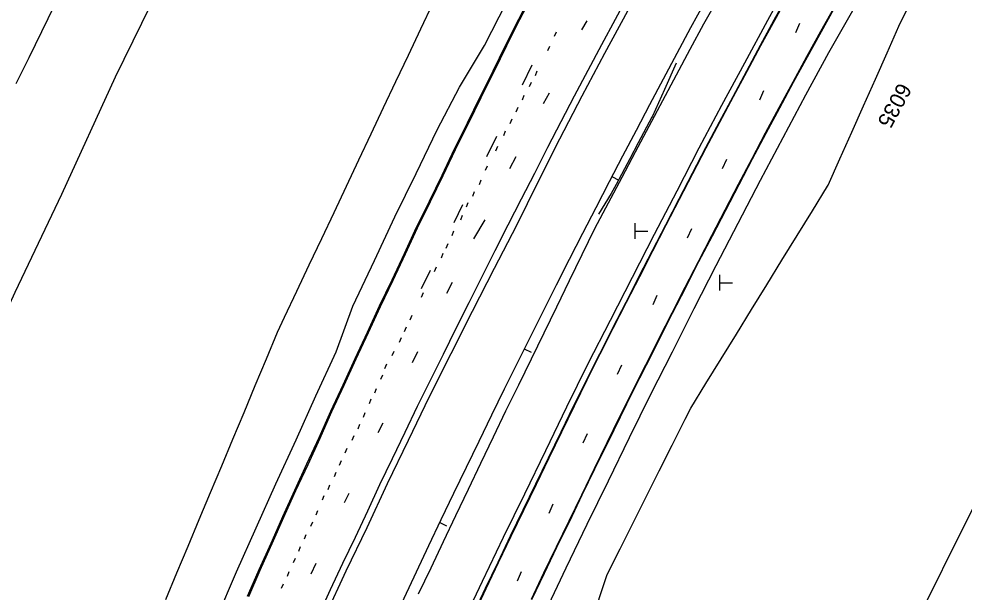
# Model space of a CAD drawing. Extents: x 2132221 to 2141942, y 535736 to 547298.
# Drawn here: x 2136377.6 to 2136866.6, y 538086.4 to 538383 of the extents above; entities that cross this region are included whole.
import ezdxf

# ---------------------------------------------------------------- set-up
doc = ezdxf.new("R2010")
doc.units = 0
for name, color, linetype in [('RD_EX_BldgApp', 7, 'Continuous'), ('RD_EX_Conc', 7, 'Continuous'), ('RD_EX_Fence_Other', 7, 'Continuous'), ('RD_EX_GuardRail', 7, 'Continuous'), ('RD_EX_Misc', 7, 'Continuous'), ('RD_EX_Road', 7, 'Continuous'), ('RD_EX_VEG', 7, 'Continuous'), ('RD_HC_Cl', 7, 'Continuous'), ('RD_HC_Data_Tic', 7, 'Continuous'), ('RD_HC_TX_Sta50', 7, 'Continuous'), ('TOPO_E_TLIML-Line', 7, 'Continuous')]:
    doc.layers.add(name, color=color, linetype=linetype)

msp = doc.modelspace()

# ---------------------------------------------------------------- linework, layer by layer
at = {"layer": 'RD_EX_BldgApp'}
for p, q in [((2136696.19, 538277.36), (2136696.19, 538273.25)), ((2136696.19, 538273.25), (2136696.19, 538269.13)), ((2136696.19, 538273.25), (2136703.05, 538273.25)), ((2136740.01, 538250.62), (2136740.01, 538246.51)), ((2136740.01, 538246.51), (2136740.01, 538242.39)), ((2136740.01, 538246.51), (2136746.87, 538246.51))]:
    msp.add_line(p, q, dxfattribs=at)
at = {"layer": 'RD_EX_Conc'}
for points in [[(2136495.93, 538084.29), (2136501.94, 538098.03), (2136508.09, 538111.72), (2136514.19, 538125.42), (2136520.29, 538139.13), (2136526.63, 538152.72), (2136532.88, 538166.36), (2136538.99, 538180.05), (2136545.27, 538193.68), (2136551.59, 538207.29), (2136557.87, 538220.91), (2136564.22, 538234.5), (2136570.66, 538248.05), (2136577.03, 538261.63), (2136583.37, 538275.23), (2136589.96, 538288.71), (2136596.5, 538302.2), (2136602.97, 538315.74), (2136609.6, 538329.2), (2136616.3, 538342.62), (2136622.9, 538356.08), (2136629.56, 538369.53), (2136636.31, 538382.93), (2136643.07, 538396.32)], [(2136612.65, 538074.77), (2136619.07, 538088.33), (2136625.52, 538101.87), (2136631.99, 538115.41), (2136638.55, 538128.9), (2136645.1, 538142.39), (2136651.64, 538155.89), (2136658.2, 538169.38), (2136664.77, 538182.87), (2136671.39, 538196.33), (2136678.1, 538209.75), (2136684.9, 538223.12), (2136691.74, 538236.47), (2136698.58, 538249.82), (2136705.4, 538263.18), (2136712.26, 538276.52), (2136719.19, 538289.82), (2136726.1, 538303.13), (2136733.02, 538316.45), (2136740.04, 538329.7), (2136747.09, 538342.94), (2136754.16, 538356.17), (2136761.28, 538369.37), (2136768.43, 538382.56), (2136775.68, 538395.69)], [(2136643.01, 538082.62), (2136649.46, 538096.16), (2136655.98, 538109.67), (2136662.55, 538123.15), (2136669.09, 538136.65), (2136675.64, 538150.14), (2136682.22, 538163.62), (2136688.83, 538177.08), (2136695.48, 538190.53), (2136702.25, 538203.91), (2136709.03, 538217.29), (2136715.81, 538230.67), (2136722.61, 538244.04), (2136729.42, 538257.4), (2136736.36, 538270.7), (2136743.31, 538283.99), (2136750.22, 538297.31), (2136757.19, 538310.59), (2136764.22, 538323.84), (2136771.3, 538337.06), (2136778.4, 538350.27), (2136785.56, 538363.45), (2136792.81, 538376.58), (2136800.14, 538389.66)]]:
    msp.add_lwpolyline(points, dxfattribs=at)
at = {"layer": 'RD_EX_Fence_Other'}
for points in [[(2136450.24, 538399.41), (2136427.31, 538352.83), (2136399.57, 538292.12), (2136375.56, 538241.34), (2136349.06, 538184.13), (2136326.14, 538129.95), (2136298.73, 538065.31), (2136267.48, 537990.84), (2136241.5, 537929.73), (2136222.24, 537881.77), (2136189.74, 537799.13)], [(2136917.56, 538219.98), (2136890.82, 538168.74), (2136867.21, 538121.82), (2136843.5, 538074.27), (2136814.83, 538016.13), (2136789.9, 537964.36), (2136765.69, 537912.51), (2136738.54, 537852.61), (2136715.83, 537801.24), (2136694.15, 537749.42), (2136674.71, 537701.68), (2136655.13, 537652.11), (2136635.21, 537599.51), (2136616.78, 537549.09), (2136595.01, 537486.59), (2136577.24, 537436.55), (2136562.65, 537393.15), (2136547.82, 537347.2), (2136530.56, 537291.65)]]:
    msp.add_lwpolyline(points, dxfattribs=at)
at = {"layer": 'RD_EX_GuardRail'}
for points in [[(2136584.35, 538085.4), (2136590.8, 538098.94), (2136597.25, 538112.48), (2136603.7, 538126.03), (2136610.15, 538139.57), (2136616.6, 538153.11), (2136623.05, 538166.65), (2136629.6, 538180.15), (2136636.16, 538193.64), (2136642.73, 538207.12), (2136649.3, 538220.61), (2136655.86, 538234.09), (2136662.43, 538247.58), (2136669, 538261.07), (2136675.56, 538274.55), (2136682.59, 538287.8), (2136689.63, 538301.05), (2136696.66, 538314.3), (2136703.7, 538327.55), (2136710.74, 538340.79), (2136717.77, 538354.04), (2136724.81, 538367.29), (2136731.91, 538380.5), (2136739.31, 538393.55)], [(2136717.66, 538360.15), (2136711.53, 538346.46), (2136705.4, 538332.77), (2136705.1, 538332.09), (2136698.03, 538318.86), (2136693.6, 538310.56), (2136686.54, 538297.33), (2136684.05, 538292.66), (2136677.44, 538281.96)]]:
    msp.add_lwpolyline(points, dxfattribs=at)
at = {"layer": 'RD_EX_Misc'}
for p, q in [((2136668.88, 538377.3), (2136671.61, 538382.08)), ((2136779.49, 538375.91), (2136781.68, 538380.74)), ((2136654.71, 538374.02), (2136655.66, 538376.36)), ((2136651.3, 538366.59), (2136652.25, 538368.93)), ((2136638.13, 538348.9), (2136643.11, 538359.21)), ((2136644.86, 538353.79), (2136645.81, 538356.13)), ((2136641.83, 538348.02), (2136642.78, 538350.36)), ((2136760.87, 538341.19), (2136763.06, 538346.02)), ((2136638.12, 538341.18), (2136639.07, 538343.52)), ((2136648.92, 538339.26), (2136652.04, 538344.74)), ((2136634.9, 538334.92), (2136635.84, 538337.27)), ((2136631.77, 538328.91), (2136632.72, 538331.25)), ((2136619.69, 538311.81), (2136624.91, 538322.26)), ((2136628.45, 538322.7), (2136629.4, 538325.05)), ((2136624.35, 538314.74), (2136625.3, 538317.08)), ((2136631.65, 538305.65), (2136634.84, 538311.82)), ((2136619.05, 538304.7), (2136619.99, 538307.05)), ((2136741.69, 538305.58), (2136743.87, 538310.42)), ((2136615.87, 538297.37), (2136616.82, 538299.72)), ((2136612.4, 538291.31), (2136613.35, 538293.66)), ((2136602.75, 538277.66), (2136607.3, 538286.99)), ((2136609.13, 538285.74), (2136610.08, 538288.09)), ((2136606.2, 538279.05), (2136607.15, 538281.39)), ((2136612.9, 538269.24), (2136618.81, 538279.07)), ((2136601.7, 538270.99), (2136602.64, 538273.34)), ((2136723.49, 538269.7), (2136725.68, 538274.53)), ((2136598.67, 538264.39), (2136599.62, 538266.74)), ((2136596.18, 538259.41), (2136597.13, 538261.75)), ((2136585.81, 538243.58), (2136590.54, 538253.07)), ((2136592.67, 538252.37), (2136593.62, 538254.71)), ((2136599.04, 538241.16), (2136601.97, 538246.85)), ((2136585.92, 538239.03), (2136586.87, 538241.37)), ((2136705.67, 538235.26), (2136707.86, 538240.09)), ((2136580.09, 538227.33), (2136581.04, 538229.68)), ((2136577.16, 538221.27), (2136578.11, 538223.62)), ((2136574.57, 538215.75), (2136575.52, 538218.1)), ((2136570.78, 538208.79), (2136571.73, 538211.13)), ((2136581.17, 538205.14), (2136583.93, 538210.81)), ((2136566.94, 538202.11), (2136567.89, 538204.46)), ((2136687.33, 538199.19), (2136689.51, 538204.03)), ((2136564.89, 538196.55), (2136565.84, 538198.9)), ((2136561.73, 538189.46), (2136562.67, 538191.8)), ((2136558.93, 538184.02), (2136559.88, 538186.37)), ((2136555.85, 538176.93), (2136556.8, 538179.27)), ((2136553.03, 538170.94), (2136553.98, 538173.28)), ((2136563.51, 538168.89), (2136566.07, 538174.03)), ((2136550.04, 538165.04), (2136550.99, 538167.38)), ((2136669.5, 538163.65), (2136671.69, 538168.48)), ((2136546.45, 538158.45), (2136547.4, 538160.8)), ((2136543.48, 538152.07), (2136544.43, 538154.42)), ((2136540.8, 538146.16), (2136541.74, 538148.51)), ((2136537.52, 538139.51), (2136538.47, 538141.86)), ((2136534.59, 538134.04), (2136535.54, 538136.38)), ((2136546.05, 538132.81), (2136548.42, 538137.53)), ((2136651.87, 538127.26), (2136654.06, 538132.09)), ((2136531.38, 538126.29), (2136532.33, 538128.63)), ((2136528.7, 538120.47), (2136529.64, 538122.82)), ((2136525.33, 538113.87), (2136526.27, 538116.22)), ((2136522.38, 538107.57), (2136523.33, 538109.92)), ((2136519.69, 538101.61), (2136520.64, 538103.96)), ((2136528.73, 538095.8), (2136531.3, 538101.36)), ((2136516.52, 538094.67), (2136517.47, 538097.02)), ((2136635.5, 538092.23), (2136637.69, 538097.06)), ((2136513.53, 538088.37), (2136514.48, 538090.72))]:
    msp.add_line(p, q, dxfattribs=at)
for points in [[(2136496.47, 538084.05), (2136502.47, 538097.8), (2136508.63, 538111.48), (2136514.73, 538125.18), (2136520.82, 538138.89), (2136527.17, 538152.48), (2136533.42, 538166.11), (2136539.53, 538179.81), (2136545.8, 538193.44), (2136552.12, 538207.04), (2136558.4, 538220.66), (2136564.75, 538234.25), (2136571.18, 538247.8), (2136577.56, 538261.38), (2136583.9, 538274.97), (2136590.49, 538288.45), (2136597.03, 538301.95), (2136603.49, 538315.48), (2136610.12, 538328.94), (2136616.83, 538342.36), (2136623.43, 538355.83), (2136630.08, 538369.27), (2136636.83, 538382.67), (2136643.6, 538396.05)], [(2136532.61, 538074.1), (2136538.87, 538087.73), (2136545.17, 538101.34), (2136551.65, 538114.87), (2136558.06, 538128.44), (2136564.4, 538142.03), (2136570.86, 538155.57), (2136577.35, 538169.09), (2136583.87, 538182.6), (2136590.48, 538196.06), (2136597.19, 538209.48), (2136603.9, 538222.9), (2136610.61, 538236.31), (2136617.34, 538249.72), (2136624.07, 538263.12), (2136630.81, 538276.52), (2136637.64, 538289.88), (2136644.48, 538303.23), (2136651.33, 538316.57), (2136658.19, 538329.91), (2136665.05, 538343.25), (2136672.1, 538356.49), (2136679.18, 538369.71), (2136686.3, 538382.91), (2136693.41, 538396.13)], [(2136612.88, 538074.67), (2136619.3, 538088.22), (2136625.75, 538101.77), (2136632.22, 538115.3), (2136638.78, 538128.79), (2136645.33, 538142.28), (2136651.86, 538155.78), (2136658.42, 538169.27), (2136664.99, 538182.76), (2136671.61, 538196.22), (2136678.32, 538209.64), (2136685.12, 538223), (2136691.96, 538236.35), (2136698.8, 538249.7), (2136705.62, 538263.07), (2136712.49, 538276.4), (2136719.41, 538289.71), (2136726.32, 538303.02), (2136733.24, 538316.33), (2136740.26, 538329.58), (2136747.31, 538342.83), (2136754.38, 538356.05), (2136761.5, 538369.26), (2136768.65, 538382.44), (2136775.9, 538395.57)], [(2136642.72, 538082.75), (2136649.17, 538096.3), (2136655.69, 538109.81), (2136662.26, 538123.29), (2136668.8, 538136.79), (2136675.35, 538150.28), (2136681.93, 538163.76), (2136688.55, 538177.23), (2136695.19, 538190.67), (2136701.96, 538204.06), (2136708.75, 538217.44), (2136715.53, 538230.82), (2136722.32, 538244.19), (2136729.14, 538257.55), (2136736.08, 538270.85), (2136743.03, 538284.14), (2136749.94, 538297.45), (2136756.91, 538310.74), (2136763.93, 538323.99), (2136771.01, 538337.21), (2136778.12, 538350.42), (2136785.28, 538363.6), (2136792.53, 538376.73), (2136799.86, 538389.82)]]:
    msp.add_lwpolyline(points, dxfattribs=at)
at = {"layer": 'RD_EX_Road'}
for points in [[(2136606.67, 538069.44), (2136617.39, 538092.03), (2136628.25, 538114.79), (2136639.29, 538137.23), (2136650.2, 538159.72), (2136661.13, 538182.2), (2136672.15, 538204.65), (2136683.73, 538227.17), (2136695.13, 538249.42), (2136706.48, 538271.69), (2136718.11, 538294.01), (2136729.6, 538316.22), (2136741.3, 538338.32), (2136753.09, 538360.36), (2136764.99, 538382.35), (2136777.05, 538404.25)], [(2136479.98, 538073.11), (2136490.13, 538096.78), (2136500.36, 538119.61), (2136510.5, 538142.48), (2136521.07, 538165.13), (2136531.2, 538188), (2136541.75, 538210.67), (2136550.4, 538234.42), (2136561.54, 538257.94), (2136572.12, 538280.62), (2136583.18, 538303.04), (2136593.98, 538325.6), (2136605.59, 538347.74), (2136618.47, 538369.22), (2136629.83, 538391.5)], [(2136536.47, 538074.61), (2136546.91, 538097.32), (2136557.71, 538119.87), (2136568.32, 538142.51), (2136579.12, 538165.05), (2136590.04, 538187.55), (2136601.19, 538209.85), (2136612.34, 538231.79), (2136623.64, 538254.09), (2136635.17, 538276.27), (2136646.22, 538298.7), (2136657.48, 538321.02), (2136669.03, 538343.19), (2136680.8, 538365.25), (2136692.64, 538387.27)], [(2136650.24, 538076.62), (2136660.7, 538099.01), (2136671.66, 538121.48), (2136682.55, 538143.98), (2136693.48, 538166.46), (2136704.58, 538188.85), (2136715.72, 538210.76), (2136726.96, 538233.1), (2136738.3, 538255.38), (2136749.8, 538277.34), (2136761.28, 538299.53), (2136772.97, 538321.62), (2136784.78, 538343.66), (2136796.68, 538365.65), (2136809.11, 538387.36)]]:
    msp.add_lwpolyline(points, dxfattribs=at)
at = {"layer": 'RD_EX_VEG'}
for points in [[(2136591.72, 538391.21), (2136585.31, 538377.64), (2136578.91, 538364.08), (2136572.5, 538350.52), (2136566.1, 538336.95), (2136559.69, 538323.39), (2136553.28, 538309.83), (2136546.88, 538296.26), (2136540.47, 538282.7), (2136534.07, 538269.14), (2136527.66, 538255.57), (2136521.26, 538242.01), (2136514.85, 538228.45), (2136511.22, 538220.75), (2136505.44, 538206.9), (2136499.66, 538193.06), (2136493.88, 538179.22), (2136488.1, 538165.38), (2136482.32, 538151.54), (2136476.54, 538137.69), (2136470.76, 538123.85), (2136464.98, 538110.01), (2136459.2, 538096.17), (2136453.42, 538082.33)], [(2136674.39, 538072.42), (2136679.09, 538086.67), (2136681.99, 538095.44), (2136688.71, 538108.85), (2136695.44, 538122.26), (2136702.16, 538135.67), (2136708.88, 538149.08), (2136715.6, 538162.49), (2136722.33, 538175.9), (2136725.17, 538181.57), (2136733.04, 538194.34), (2136740.91, 538207.11), (2136748.78, 538219.88), (2136756.65, 538232.65), (2136764.53, 538245.42), (2136772.4, 538258.19), (2136780.27, 538270.96), (2136788.14, 538283.73), (2136796.01, 538296.5), (2136796.31, 538296.99), (2136802.41, 538310.69), (2136808.51, 538324.4), (2136814.61, 538338.1), (2136820.71, 538351.8), (2136826.81, 538365.51), (2136832.91, 538379.21), (2136833.61, 538380.79), (2136840.26, 538394.23)]]:
    msp.add_lwpolyline(points, dxfattribs=at)
at = {"layer": 'RD_HC_Cl'}
msp.add_arc((2141773.22, 535656.94), 5734.92, 149.115721, 168.327797, dxfattribs=at)
at = {"layer": 'RD_HC_Data_Tic'}
for p, q in [((2136684.4, 538301.39), (2136687.95, 538299.55)), ((2136639.06, 538212.26), (2136642.65, 538210.48)), ((2136595.29, 538122.35), (2136598.9, 538120.63))]:
    msp.add_line(p, q, dxfattribs=at)
at = {"layer": 'TOPO_E_TLIML-Line'}
msp.add_lwpolyline([(2136395.79, 538389.83), (2136389.22, 538376.35), (2136382.64, 538362.87), (2136376.07, 538349.38)], dxfattribs=at)

# ---------------------------------------------------------------- texts
at = {"layer": 'RD_HC_TX_Sta50'}
msp.add_text('6035', height=8, rotation=241.5418, dxfattribs=at).set_placement((2136832.88, 538350.53))

doc.saveas('drawing.dxf')
